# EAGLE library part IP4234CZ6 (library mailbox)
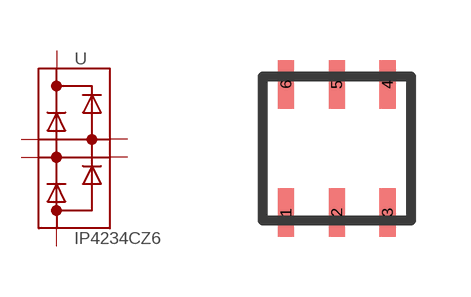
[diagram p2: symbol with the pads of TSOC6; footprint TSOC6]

Designator prefix -

## IP4234CZ6  [TSOC6]
1  IN1  pas
2  GND  pwr
3  OUT1  pas
4  OUT2  pas
5  VDD  pwr
6  IN2  pas

## Footprint TSOC6 (pad centres in mm)
TSOC 6
smd 0.406 x 1.219: 1 -1.27,-1.6; 2 0,-1.6; 3 1.27,-1.6; 4 1.27,1.6; 5 0,1.6; 6 -1.27,1.6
